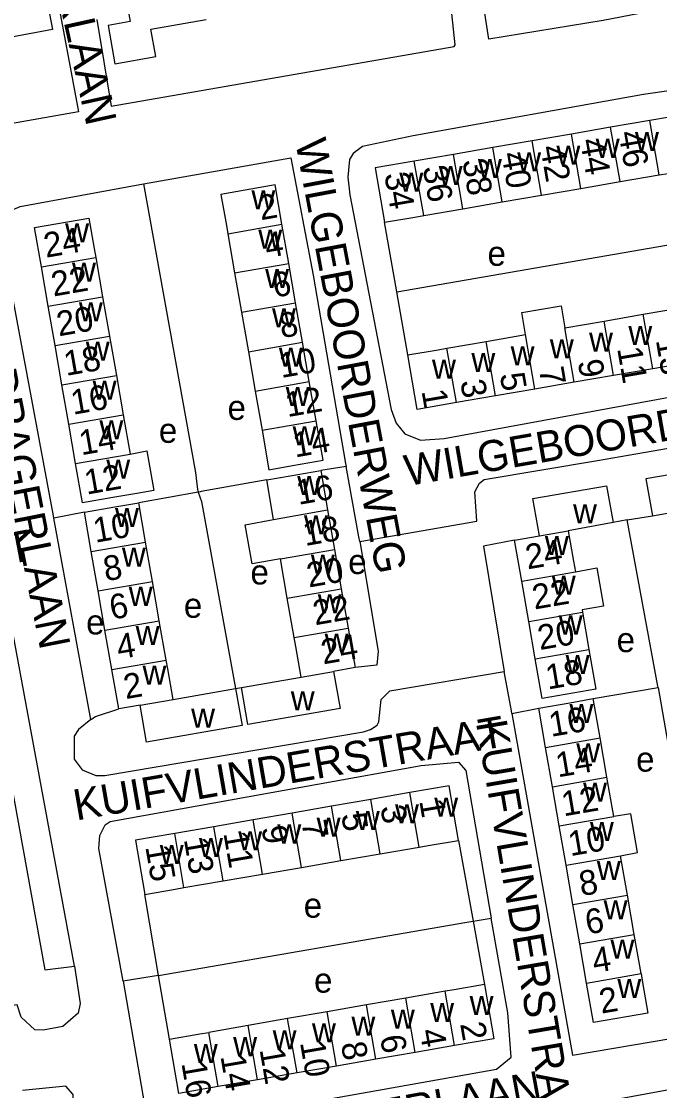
# Model space of a CAD drawing. Extents: x 162883 to 165538, y 383986 to 385172.
# Drawn here: x 164107.9 to 164211.1, y 384571.7 to 384744.4 of the extents above; entities that cross this region are included whole.
import ezdxf

# ---------------------------------------------------------------- set-up
doc = ezdxf.new("R2010")
doc.units = 0
for name, color, linetype in [('BLT_Basislijn', 7, 'Continuous'), ('BLT_Bebouwing', 7, 'Continuous'), ('BLT_Centroide', 7, 'Continuous'), ('BLT_Huisnummer', 7, 'Continuous'), ('BLT_Huisnummer_ tussenligend', 7, 'Continuous'), ('BLT_Onderverdeling_panden', 7, 'Continuous'), ('BLT_Straatnaam', 7, 'Continuous')]:
    doc.layers.add(name, color=color, linetype=linetype)

msp = doc.modelspace()

# ---------------------------------------------------------------- linework, layer by layer
at = {"layer": 'BLT_Basislijn'}
for p, q in [((164168.6, 384700.69), (164166.62, 384711.92)), ((164168.6, 384700.69), (164222.14, 384709.97)), ((164170.39, 384690.49), (164168.6, 384700.69)), ((164207.26, 384674.54), (164225.48, 384677.63)), ((164201.06, 384673.45), (164207.26, 384674.54)), ((164160.42, 384672.49), (164156.32, 384671.83)), ((164136.53, 384668.35), (164126.91, 384666.62)), ((164118.13, 384665.08), (164113.19, 384664.11)), ((164205.88, 384663.84), (164209.93, 384664.52)), ((164119.18, 384631.6), (164113.19, 384664.11)), ((164205.88, 384663.84), (164203.57, 384663.44)), ((164142.56, 384636.63), (164143.53, 384636.8)), ((164200.37, 384634.98), (164210.85, 384636.76)), ((164187.23, 384632.57), (164191.58, 384633.45)), ((164178.59, 384612.09), (164180.96, 384599.05)), ((164130.11, 384590.26), (164127.89, 384603.36)), ((164180.96, 384599.05), (164183.87, 384599.5)), ((164180.96, 384599.05), (164182.81, 384588.81)), ((164131.86, 384579.98), (164130.11, 384590.26))]:
    msp.add_line(p, q, dxfattribs=at)
for points in [[(164095.97, 384842.34), (164093.47, 384839.82), (164090.83, 384834.95), (164089.67, 384829.38), (164089.81, 384824.45), (164090.64, 384821.59), (164101.2, 384802.81), (164103.99, 384793.49), (164113.36, 384750.3), (164117.16, 384729.76), (164088.15, 384724.64)], [(164218.19, 384747.63), (164202, 384744.49), (164183.49, 384741.49), (164179.63, 384766.7), (164176.36, 384776.66), (164174.75, 384784.35), (164174.11, 384794.16), (164174.69, 384805.19), (164174.5, 384812.21), (164174.11, 384815.48), (164172.03, 384823.03), (164170.73, 384825.96)], [(164120.14, 384744.7), (164122.44, 384730.7), (164177.88, 384740.34), (164178.07, 384740.58), (164176.29, 384757.32)], [(164217.84, 384733.93), (164208.48, 384732.56), (164171.26, 384725.9), (164163.09, 384724.16), (164161.59, 384723.02), (164160.96, 384722.06), (164160.7, 384719.23), (164161.02, 384716.34), (164167.7, 384681.66), (164168.5, 384679.45), (164169.93, 384677.77), (164172.47, 384676.74), (164176.29, 384676.98), (164226.46, 384686.21)], [(164127.69, 384718.14), (164151.47, 384722.32), (164155.12, 384703.37), (164160.33, 384672.96), (164160.42, 384672.49)], [(164113.19, 384664.11), (164113.12, 384664.52), (164105.02, 384707.84), (164105.09, 384712.51), (164106.61, 384713.98), (164107.73, 384714.46), (164127.69, 384718.14)], [(164127.69, 384718.14), (164136.09, 384671.53), (164136.39, 384668.76), (164136.53, 384668.35)], [(164162.63, 384660.34), (164181.57, 384663.65), (164181.22, 384668.39), (164181.97, 384669.79), (164182.72, 384670.35), (164201.06, 384673.45)], [(164162.63, 384660.34), (164162.5, 384661.14), (164160.42, 384672.49)], [(164147.59, 384670.3), (164136.99, 384668.43), (164136.84, 384668.41), (164136.53, 384668.35)], [(164136.53, 384668.35), (164137.07, 384666.81), (164142.56, 384636.63)], [(164210.85, 384636.76), (164210.81, 384637), (164205.88, 384663.84)], [(164162.63, 384660.34), (164165.63, 384642.66), (164165.39, 384640.36), (164161.88, 384639.99)], [(164187.66, 384660.6), (164182.63, 384659.61), (164185.99, 384639.37)], [(164116.53, 384591.78), (164106.51, 384645.99), (164104.8, 384653.59), (164100.26, 384652.89)], [(164100.26, 384652.89), (164101.78, 384646.05), (164111.74, 384591.16), (164116.53, 384591.78)], [(164119.18, 384631.6), (164117.18, 384630.02), (164116.47, 384628.92), (164116.48, 384625.21), (164117.75, 384623.46), (164119.98, 384622.57), (164121.41, 384622.57), (164163.24, 384629.64), (164164.39, 384629.97), (164165.42, 384630.7), (164165.74, 384631.24), (164166.11, 384634.82), (164167.48, 384636.25), (164185.99, 384639.37)], [(164187.23, 384632.57), (164187.15, 384633.02), (164185.99, 384639.37)], [(164210.85, 384636.76), (164214.03, 384618.46), (164214.72, 384611.85)], [(164119.18, 384631.6), (164119.91, 384632.09), (164123.67, 384633.31)], [(164187.23, 384632.57), (164197, 384577.38), (164219.61, 384581.22)], [(164124.37, 384589.37), (164120.45, 384610.8), (164120.63, 384612.87), (164121.47, 384614.59), (164122.31, 384615.11), (164172.56, 384624.17), (164178.58, 384624.7), (164179.79, 384623.37), (164183.87, 384599.5)], [(164116.53, 384591.78), (164117.43, 384585.76), (164117.11, 384584.17), (164114.63, 384582.01), (164111.45, 384581.42), (164110.11, 384581.47), (164107.89, 384583.52), (164107.25, 384585.51), (164095.36, 384583.76), (164062.87, 384578), (164062.43, 384577.89), (164062.25, 384575.99), (164061.75, 384574.85), (164059.35, 384574.4), (164057.81, 384576.68), (164057.46, 384578.28), (164050.3, 384616.85)], [(164124.37, 384589.37), (164127.82, 384569.36), (164128.83, 384567.74), (164129.82, 384566.66), (164130.54, 384566.31), (164134.71, 384566.26), (164184.72, 384575.13), (164187.11, 384577.07), (164186.59, 384584.21), (164183.87, 384599.5)], [(164130.11, 384590.26), (164179.96, 384598.89), (164180.96, 384599.05)], [(164130.11, 384590.26), (164129.38, 384590.13), (164124.37, 384589.37)], [(164250.47, 384573.67), (164250.27, 384574.53), (164249.08, 384576.32), (164247.1, 384577.51), (164244.79, 384577.71), (164126.03, 384555.88), (164121.95, 384556.13), (164120.84, 384556.55), (164118.27, 384559.19), (164117.27, 384561.39), (164113.93, 384561.01), (164112.88, 384567.21), (164114.89, 384567.71), (164116.32, 384568.96), (164116.32, 384571.03), (164115.14, 384572.4), (164108.09, 384571.67)]]:
    msp.add_lwpolyline(points, dxfattribs=at)
at = {"layer": 'BLT_Bebouwing'}
for p, q in [((164209.54, 384728.36), (164203.19, 384727.27)), ((164203.19, 384727.27), (164196.84, 384726.17)), ((164190.49, 384725.08), (164184.15, 384723.98)), ((164196.84, 384726.17), (164190.49, 384725.08)), ((164184.15, 384723.98), (164177.8, 384722.89)), ((164177.8, 384722.89), (164171.45, 384721.8)), ((164198.36, 384717.39), (164204.7, 384718.49)), ((164204.7, 384718.49), (164211.05, 384719.58)), ((164185.66, 384715.2), (164192.01, 384716.3)), ((164192.01, 384716.3), (164198.36, 384717.39)), ((164179.32, 384714.11), (164185.66, 384715.2)), ((164172.97, 384713.01), (164179.32, 384714.11)), ((164151.16, 384705.25), (164150.05, 384711.61)), ((164141.31, 384710.08), (164142.41, 384703.73)), ((164119.96, 384706.25), (164121.07, 384699.89)), ((164112.27, 384698.36), (164111.16, 384704.71)), ((164152.26, 384698.9), (164151.16, 384705.25)), ((164142.41, 384703.73), (164143.52, 384697.38)), ((164121.07, 384699.89), (164122.18, 384693.54)), ((164113.38, 384692), (164112.27, 384698.36)), ((164143.52, 384697.38), (164144.63, 384691.02)), ((164153.37, 384692.55), (164152.26, 384698.9)), ((164208.47, 384697.06), (164214.82, 384698.15)), ((164195.78, 384694.87), (164202.12, 384695.96)), ((164202.12, 384695.96), (164208.47, 384697.06)), ((164122.18, 384693.54), (164123.29, 384687.18)), ((164154.48, 384686.2), (164153.37, 384692.55)), ((164176.73, 384691.59), (164183.08, 384692.68)), ((164183.08, 384692.68), (164189.43, 384693.77)), ((164114.49, 384685.65), (164113.38, 384692)), ((164144.63, 384691.02), (164145.74, 384684.67)), ((164216.33, 384689.36), (164209.99, 384688.26)), ((164123.29, 384687.18), (164124.4, 384680.83)), ((164203.64, 384687.17), (164197.29, 384686.08)), ((164209.99, 384688.26), (164203.64, 384687.17)), ((164115.6, 384679.29), (164114.49, 384685.65)), ((164155.59, 384679.84), (164154.48, 384686.2)), ((164197.29, 384686.08), (164190.95, 384684.98)), ((164145.74, 384684.67), (164146.85, 384678.32)), ((164184.6, 384683.89), (164178.25, 384682.79)), ((164190.95, 384684.98), (164184.6, 384683.89)), ((164124.4, 384680.83), (164125.51, 384674.48)), ((164116.7, 384672.94), (164115.6, 384679.29)), ((164156.32, 384671.83), (164157.43, 384665.46)), ((164148.7, 384663.94), (164147.59, 384670.3)), ((164128.02, 384660.26), (164126.91, 384666.62)), ((164119.24, 384658.73), (164118.13, 384665.08)), ((164157.43, 384665.46), (164158.54, 384659.09)), ((164129.12, 384653.91), (164128.02, 384660.26)), ((164188.82, 384653.97), (164187.66, 384660.6)), ((164120.34, 384652.38), (164119.24, 384658.73)), ((164150.92, 384651.2), (164149.81, 384657.57)), ((164158.54, 384659.09), (164159.65, 384652.72)), ((164121.45, 384646.02), (164120.34, 384652.38)), ((164130.23, 384647.55), (164129.12, 384653.91)), ((164159.65, 384652.72), (164160.76, 384646.36)), ((164189.95, 384647.46), (164188.82, 384653.97)), ((164152.04, 384644.84), (164150.92, 384651.2)), ((164198.63, 384648.97), (164199.68, 384642.91)), ((164131.34, 384641.2), (164130.23, 384647.55)), ((164191.01, 384641.4), (164189.95, 384647.46)), ((164122.56, 384639.67), (164121.45, 384646.02)), ((164160.76, 384646.36), (164161.88, 384639.99)), ((164123.67, 384633.31), (164122.56, 384639.67)), ((164192.68, 384627.1), (164191.58, 384633.45)), ((164201.48, 384628.63), (164200.37, 384634.98)), ((164202.58, 384622.29), (164201.48, 384628.63)), ((164193.79, 384620.76), (164192.68, 384627.1)), ((164203.69, 384615.94), (164202.58, 384622.29)), ((164170.74, 384619.8), (164164.4, 384618.7)), ((164194.89, 384614.41), (164193.79, 384620.76)), ((164164.4, 384618.7), (164158.07, 384617.6)), ((164151.73, 384616.5), (164145.39, 384615.4)), ((164158.07, 384617.6), (164151.73, 384616.5)), ((164145.39, 384615.4), (164139.05, 384614.3)), ((164195.99, 384608.07), (164194.89, 384614.41)), ((164139.05, 384614.3), (164132.72, 384613.2)), ((164165.92, 384609.9), (164172.26, 384610.99)), ((164159.58, 384608.81), (164165.92, 384609.9)), ((164205.9, 384603.25), (164204.79, 384609.6)), ((164146.9, 384606.63), (164153.24, 384607.72)), ((164153.24, 384607.72), (164159.58, 384608.81)), ((164197.1, 384601.72), (164195.99, 384608.07)), ((164140.56, 384605.54), (164146.9, 384606.63)), ((164134.22, 384604.45), (164140.56, 384605.54)), ((164207, 384596.91), (164205.9, 384603.25)), ((164198.2, 384595.38), (164197.1, 384601.72)), ((164199.31, 384589.03), (164198.2, 384595.38)), ((164208.11, 384590.56), (164207, 384596.91)), ((164176.44, 384587.71), (164170.08, 384586.61)), ((164163.71, 384585.5), (164157.34, 384584.4)), ((164170.08, 384586.61), (164163.71, 384585.5)), ((164150.97, 384583.29), (164144.6, 384582.18)), ((164157.34, 384584.4), (164150.97, 384583.29)), ((164144.6, 384582.18), (164138.23, 384581.08)), ((164177.96, 384578.94), (164171.6, 384577.84)), ((164165.23, 384576.73), (164158.86, 384575.63)), ((164171.6, 384577.84), (164165.23, 384576.73)), ((164158.86, 384575.63), (164152.49, 384574.52)), ((164146.12, 384573.42), (164139.75, 384572.31)), ((164152.49, 384574.52), (164146.12, 384573.42))]:
    msp.add_line(p, q, dxfattribs=at)
for points in [[(164108.94, 384750), (164109.14, 384748.81), (164111.8, 384749.3), (164112.94, 384743.05), (164106.32, 384741.84), (164105.2, 384747.94), (164096.89, 384746.43)], [(164124.49, 384750), (164125.5, 384744.36), (164121.94, 384743.73), (164123.03, 384737.53), (164129.65, 384738.69), (164128.88, 384743.09), (164137.78, 384744.66)], [(164211.05, 384719.58), (164212.47, 384719.82), (164217.39, 384720.67), (164215.88, 384729.46), (164209.54, 384728.36)], [(164171.45, 384721.8), (164165.11, 384720.7), (164166.62, 384711.92)], [(164150.05, 384711.61), (164148.94, 384717.96), (164140.2, 384716.43), (164141.07, 384711.42), (164141.31, 384710.08)], [(164166.62, 384711.92), (164171.55, 384712.77), (164172.97, 384713.01)], [(164111.16, 384704.71), (164110.05, 384711.07), (164118.86, 384712.6), (164119.71, 384707.68), (164119.96, 384706.25)], [(164189.43, 384693.77), (164188.85, 384697.33), (164195.17, 384698.42), (164195.78, 384694.87)], [(164170.39, 384690.49), (164175.32, 384691.34), (164176.73, 384691.59)], [(164178.25, 384682.79), (164171.9, 384681.7), (164170.39, 384690.49)], [(164146.85, 384678.32), (164147.95, 384671.96), (164151.77, 384672.63), (164156.7, 384673.49), (164155.59, 384679.84)], [(164125.51, 384674.48), (164128.21, 384675.03), (164129.32, 384668.59), (164126.61, 384668.12), (164122.74, 384667.45), (164117.81, 384666.59), (164116.7, 384672.94)], [(164147.59, 384670.3), (164151.4, 384670.97), (164156.32, 384671.83)], [(164221.85, 384666.62), (164220.82, 384672.54), (164208.9, 384670.46), (164209.93, 384664.52)], [(164191.66, 384661.3), (164190.62, 384667.28), (164202.54, 384669.36), (164203.57, 384663.44)], [(164118.13, 384665.08), (164123.05, 384665.94), (164126.91, 384666.62)], [(164209.93, 384664.52), (164216.93, 384665.77)], [(164149.81, 384657.57), (164145.23, 384656.74), (164144.12, 384663.05), (164148.7, 384663.94)], [(164203.57, 384663.44), (164196.34, 384662.11)], [(164187.66, 384660.6), (164191.66, 384661.3)], [(164196.34, 384662.11), (164197.2, 384657.19), (164197.5, 384655.48)], [(164197.5, 384655.48), (164200.97, 384656.09), (164202.05, 384649.91), (164198.57, 384649.31), (164198.63, 384648.97)], [(164153.15, 384638.47), (164152.29, 384643.39), (164152.04, 384644.84)], [(164199.68, 384642.91), (164200.8, 384636.5), (164197.05, 384635.85), (164192.12, 384634.99), (164191.01, 384641.4)], [(164132.45, 384634.84), (164131.59, 384639.77), (164131.34, 384641.2)], [(164158.4, 384639.38), (164159.44, 384633.4), (164144.56, 384630.8), (164143.53, 384636.8)], [(164161.88, 384639.99), (164158.4, 384639.38)], [(164143.53, 384636.8), (164153.15, 384638.47)], [(164142.56, 384636.63), (164143.6, 384630.63), (164128.18, 384627.94), (164127.14, 384633.93)], [(164132.45, 384634.84), (164142.56, 384636.63)], [(164127.14, 384633.93), (164123.67, 384633.31)], [(164191.58, 384633.45), (164196.58, 384634.32), (164200.37, 384634.98)], [(164178.59, 384612.09), (164177.06, 384620.89), (164170.74, 384619.8)], [(164204.79, 384609.6), (164207.54, 384610.11), (164206.46, 384616.35), (164203.69, 384615.94)], [(164132.72, 384613.2), (164126.37, 384612.1), (164127.89, 384603.36)], [(164172.26, 384610.99), (164173.67, 384611.24), (164178.59, 384612.09)], [(164127.89, 384603.36), (164132.81, 384604.21), (164134.22, 384604.45)], [(164208.11, 384590.56), (164208.36, 384589.11), (164209.22, 384584.18), (164200.41, 384582.68), (164199.31, 384589.03)], [(164182.81, 384588.81), (164177.88, 384587.96), (164176.44, 384587.71)], [(164182.81, 384588.81), (164184.33, 384580.05), (164177.96, 384578.94)], [(164131.86, 384579.98), (164136.79, 384580.83), (164138.23, 384581.08)], [(164139.75, 384572.31), (164133.38, 384571.21), (164131.86, 384579.98)]]:
    msp.add_lwpolyline(points, dxfattribs=at)
at = {"layer": 'BLT_Onderverdeling_panden'}
for p, q in [((164211.05, 384719.58), (164209.54, 384728.36)), ((164204.7, 384718.49), (164203.19, 384727.27)), ((164192.01, 384716.3), (164190.49, 384725.08)), ((164198.36, 384717.39), (164196.84, 384726.17)), ((164185.66, 384715.2), (164184.15, 384723.98)), ((164172.97, 384713.01), (164171.45, 384721.8)), ((164179.32, 384714.11), (164177.8, 384722.89)), ((164141.31, 384710.08), (164150.05, 384711.61)), ((164111.16, 384704.71), (164119.96, 384706.25)), ((164142.41, 384703.73), (164151.16, 384705.25)), ((164112.27, 384698.36), (164121.07, 384699.89)), ((164143.52, 384697.38), (164152.26, 384698.9)), ((164203.64, 384687.17), (164202.12, 384695.96)), ((164209.99, 384688.26), (164208.47, 384697.06)), ((164197.29, 384686.08), (164195.78, 384694.87)), ((164113.38, 384692), (164122.18, 384693.54)), ((164144.63, 384691.02), (164153.37, 384692.55)), ((164184.6, 384683.89), (164183.08, 384692.68)), ((164190.95, 384684.98), (164189.43, 384693.77)), ((164178.25, 384682.79), (164176.73, 384691.59)), ((164114.49, 384685.65), (164123.29, 384687.18)), ((164145.74, 384684.67), (164154.48, 384686.2)), ((164115.6, 384679.29), (164124.4, 384680.83)), ((164146.85, 384678.32), (164155.59, 384679.84)), ((164116.7, 384672.94), (164125.51, 384674.48)), ((164148.7, 384663.94), (164157.43, 384665.46)), ((164191.66, 384661.3), (164196.34, 384662.11)), ((164119.24, 384658.73), (164128.02, 384660.26)), ((164149.81, 384657.57), (164158.54, 384659.09)), ((164188.82, 384653.97), (164197.5, 384655.48)), ((164120.34, 384652.38), (164129.12, 384653.91)), ((164150.92, 384651.2), (164159.65, 384652.72)), ((164189.95, 384647.46), (164198.63, 384648.97)), ((164121.45, 384646.02), (164130.23, 384647.55)), ((164152.04, 384644.84), (164160.76, 384646.36)), ((164191.01, 384641.4), (164199.68, 384642.91)), ((164122.56, 384639.67), (164131.34, 384641.2)), ((164153.15, 384638.47), (164158.4, 384639.38)), ((164127.14, 384633.93), (164132.45, 384634.84)), ((164192.68, 384627.1), (164201.48, 384628.63)), ((164193.79, 384620.76), (164202.58, 384622.29)), ((164172.26, 384610.99), (164170.74, 384619.8)), ((164165.92, 384609.9), (164164.4, 384618.7)), ((164153.24, 384607.72), (164151.73, 384616.5)), ((164159.58, 384608.81), (164158.07, 384617.6)), ((164146.9, 384606.63), (164145.39, 384615.4)), ((164194.89, 384614.41), (164203.69, 384615.94)), ((164134.22, 384604.45), (164132.72, 384613.2)), ((164140.56, 384605.54), (164139.05, 384614.3)), ((164195.99, 384608.07), (164204.79, 384609.6)), ((164197.1, 384601.72), (164205.9, 384603.25)), ((164198.2, 384595.38), (164207, 384596.91)), ((164199.31, 384589.03), (164208.11, 384590.56)), ((164177.96, 384578.94), (164176.44, 384587.71)), ((164165.23, 384576.73), (164163.71, 384585.5)), ((164171.6, 384577.84), (164170.08, 384586.61)), ((164152.49, 384574.52), (164150.97, 384583.29)), ((164158.86, 384575.63), (164157.34, 384584.4)), ((164146.12, 384573.42), (164144.6, 384582.18)), ((164139.75, 384572.31), (164138.23, 384581.08))]:
    msp.add_line(p, q, dxfattribs=at)

# ---------------------------------------------------------------- texts
at = {"layer": 'BLT_Centroide'}
for s, p in [('w', (164200.78, 384722.33)), ('w', (164207.12, 384723.42)), ('w', (164188.08, 384720.14)), ('w', (164194.42, 384721.23)), ('w', (164181.73, 384719.05)), ('w', (164169.03, 384716.86)), ('w', (164175.39, 384717.95)), ('w', (164145.12, 384714.03)), ('w', (164115.01, 384708.66)), ('w', (164146.23, 384707.66)), ('e', (164183.29, 384704.89)), ('w', (164116.12, 384702.31)), ('w', (164147.34, 384701.31)), ('w', (164117.23, 384695.94)), ('w', (164148.45, 384694.97)), ('w', (164199.7, 384691.02)), ('w', (164206.05, 384692.12)), ('w', (164118.34, 384689.59)), ('w', (164193.36, 384689.92)), ('w', (164149.55, 384688.62)), ('w', (164180.67, 384687.73)), ('w', (164187.02, 384688.83)), ('w', (164174.31, 384686.64)), ('w', (164119.45, 384683.25)), ('w', (164150.66, 384682.25)), ('e', (164141.26, 384680)), ('w', (164120.55, 384676.88)), ('e', (164130.16, 384676.3)), ('w', (164151.77, 384675.91)), ('w', (164121.66, 384670.53)), ('w', (164152.52, 384667.88)), ('w', (164197.11, 384663.31)), ('w', (164123.07, 384662.69)), ('w', (164153.62, 384661.5)), ('w', (164192.56, 384658.16)), ('w', (164124.18, 384656.31)), ('w', (164154.73, 384655.16)), ('e', (164160.76, 384655.11)), ('e', (164144.96, 384653.42)), ('w', (164193.67, 384651.75)), ('w', (164125.29, 384649.97)), ('e', (164134.2, 384648.04)), ('w', (164155.84, 384648.78)), ('e', (164118.4, 384645.35)), ('w', (164194.79, 384645.34)), ('w', (164126.4, 384643.62)), ('w', (164156.95, 384642.41)), ('e', (164204.15, 384642.49)), ('w', (164195.91, 384638.94)), ('w', (164127.51, 384637.25)), ('w', (164151.48, 384633.09)), ('w', (164135.37, 384630.28)), ('w', (164196.53, 384631.03)), ('w', (164197.63, 384624.69)), ('e', (164207.3, 384623.19)), ('w', (164198.73, 384618.34)), ('w', (164168.33, 384614.84)), ('w', (164174.67, 384615.94)), ('w', (164162, 384613.75)), ('w', (164149.31, 384611.58)), ('w', (164155.66, 384612.66)), ('w', (164199.84, 384612)), ('w', (164142.98, 384610.47)), ('w', (164130.3, 384608.28)), ('w', (164136.64, 384609.38)), ('w', (164200.95, 384605.66)), ('e', (164153.57, 384599.6)), ('w', (164202.05, 384599.31)), ('w', (164203.16, 384592.97)), ('e', (164155.24, 384587.49)), ('w', (164204.27, 384586.62)), ('w', (164180.39, 384583.89)), ('w', (164174.02, 384582.77)), ('w', (164161.28, 384580.56)), ('w', (164167.66, 384581.67)), ('w', (164154.91, 384579.45)), ('w', (164142.17, 384577.23)), ('w', (164148.55, 384578.36)), ('w', (164135.81, 384576.14))]:
    msp.add_text(s, height=4, dxfattribs=at).set_placement(p)
at = {"layer": 'BLT_Huisnummer'}
for s, rotation, p in [('42', 279.7868, (164191.8, 384724.06)), ('38', 279.7868, (164179.2, 384721.87)), ('34', 279.7868, (164166.59, 384719.68)), ('2', 9.8965, (164146.64, 384712.24)), ('24', 9.8966, (164111.9, 384706.18)), ('6', 9.8965, (164148.87, 384699.73)), ('20', 9.8966, (164113.98, 384693.49)), ('10', 9.8965, (164149.94, 384686.76)), ('9', 279.7811, (164197.85, 384689.47)), ('5', 279.7811, (164185.25, 384687.35)), ('16', 9.8966, (164116.29, 384680.82)), ('1', 279.7811, (164172.61, 384684.67)), ('14', 9.8965, (164152.18, 384673.92)), ('12', 9.8966, (164118.47, 384667.92)), ('16', 9.8965, (164152.73, 384666.27)), ('10', 9.8966, (164119.89, 384660.15)), ('24', 9.649, (164189.75, 384655.85)), ('20', 9.8965, (164154.4, 384652.92)), ('6', 9.8966, (164122.54, 384647.72)), ('24', 9.8965, (164156.72, 384640.5)), ('18', 9.649, (164193.02, 384636.44)), ('2', 9.8966, (164124.8, 384634.89)), ('16', 9.649, (164193.55, 384628.8)), ('1', 279.7726, (164172.24, 384618.48)), ('5', 279.7726, (164159.62, 384616.24)), ('9', 279.7726, (164146.73, 384614.18)), ('10', 9.649, (164196.68, 384609.53)), ('15', 279.7726, (164127.96, 384611.05)), ('6', 9.649, (164199.43, 384596.87)), ('2', 9.649, (164201.68, 384584.09)), ('2', 279.8413, (164178.85, 384582.45)), ('6', 279.8413, (164165.89, 384580.38)), ('10', 279.8413, (164152.96, 384579.44)), ('16', 279.8413, (164133.79, 384576.09))]:
    msp.add_text(s, height=4, rotation=rotation, dxfattribs=at).set_placement(p)
at = {"layer": 'BLT_Huisnummer_ tussenligend'}
for s, rotation, p in [('44', 279.7868, (164198.23, 384725.18)), ('46', 279.7868, (164204.44, 384726.4)), ('40', 279.7868, (164185.52, 384722.99)), ('36', 279.7868, (164172.8, 384720.78)), ('4', 9.8965, (164147.63, 384706.14)), ('22', 9.8966, (164113.11, 384699.92)), ('8', 9.8965, (164149.99, 384693.19)), ('13', 279.7811, (164210.48, 384692.88)), ('18', 9.8966, (164115.16, 384687.1)), ('11', 279.7811, (164204.23, 384691.54)), ('7', 279.7811, (164191.57, 384688.25)), ('12', 9.8965, (164150.95, 384680.44)), ('3', 279.7811, (164178.86, 384686.23)), ('14', 9.8966, (164117.62, 384674.28)), ('18', 9.8965, (164153.8, 384659.62)), ('8', 9.8966, (164121.55, 384653.93)), ('22', 9.649, (164190.86, 384649.37)), ('22', 9.8965, (164155.41, 384646.82)), ('20', 9.649, (164191.73, 384642.82)), ('4', 9.8966, (164123.68, 384641.32)), ('14', 9.649, (164194.65, 384622.25)), ('12', 9.649, (164195.59, 384615.96)), ('3', 279.7726, (164165.95, 384617.48)), ('7', 279.7726, (164153.19, 384615.04)), ('11', 279.7726, (164140.58, 384613.26)), ('13', 279.7726, (164134.19, 384612.26)), ('8', 9.649, (164198.44, 384603.08)), ('4', 9.649, (164200.56, 384590.64)), ('4', 279.8413, (164172.3, 384581.36)), ('12', 279.8413, (164146.42, 384578.32)), ('8', 279.8413, (164159.58, 384579.26)), ('14', 279.8413, (164140.1, 384577.22))]:
    msp.add_text(s, height=4, rotation=rotation, dxfattribs=at).set_placement(p)
at = {"layer": 'BLT_Straatnaam'}
for s, height, rotation, p in [('APOLLOVLINDERLAAN', 5, 282.4461, (164102.74, 384798.76)), ('WILGEBOORDERWEG', 5, 280.656, (164152.19, 384724.94)), ('WOLDRAGERLAAN', 5, 281.1931, (164099.11, 384702.8)), ('WILGEBOORDERWEG', 4.9999, 9.8944, (164170.34, 384669.3)), ('DAGVLINDERSTRAAT', 5, 10.7734, (164041.38, 384644.37)), ('KUIFVLINDERSTRAAT', 5, 9.8244, (164116.81, 384615.28)), ('KUIFVLINDERSTRAAT', 5, 279.6883, (164181.4, 384631.11)), ('SATIJNVLINDERLAAN', 5, 10.4364, (164124.03, 384557.41))]:
    msp.add_text(s, height=height, rotation=rotation, dxfattribs=at).set_placement(p)

doc.saveas('drawing.dxf')
